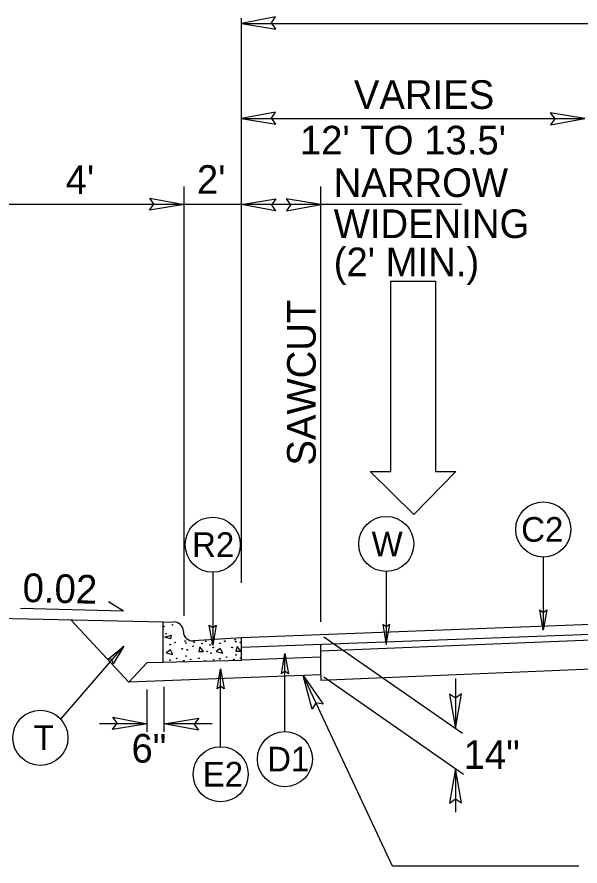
# Model space of a CAD drawing. Extents: x 573748 to 574632, y -54663 to -53209.
# Drawn here: x 574117.58 to 574147.08, y -53400.41 to -53355.94 of the extents above; entities that cross this region are included whole.
import ezdxf

# ---------------------------------------------------------------- set-up
doc = ezdxf.new("R2010")
doc.units = 0
for name, color, linetype in [('Prop Dimension', 7, 'Continuous'), ('Prop Dimension Text', 7, 'Continuous'), ('Prop Lane Arrow CELL', 7, 'Continuous'), ('Prop Terminator CELL', 7, 'Continuous'), ('Typical Arrow Superelevation CELL', 7, 'Continuous'), ('Typical Curb CELL', 7, 'Continuous'), ('Typical ID Circle CELL', 7, 'Continuous'), ('Typical Pavement Slope CELL', 7, 'Continuous'), ('Typical Terminator CELL', 7, 'Continuous'), ('Typical Text ID Circle CELL', 7, 'Continuous')]:
    doc.layers.add(name, color=color, linetype=linetype)

msp = doc.modelspace()

# ---------------------------------------------------------------- linework, layer by layer
at = {"layer": 'Prop Dimension'}
for p, q in [((574129.334, -53385.568), (574129.334, -53356.007)), ((574129.334, -53356.275), (574174.334, -53356.275)), ((574129.334, -53361.256), (574147.334, -53361.256)), ((574126.334, -53387.309), (574126.334, -53364.825)), ((574133.497, -53387.622), (574133.497, -53364.825)), ((574126.334, -53365.76), (574115.581, -53365.76)), ((574140.869, -53365.76), (574126.334, -53365.76)), ((574133.497, -53389.142), (574174.334, -53387.48)), ((574133.65, -53388.4), (574140.917, -53393.451)), ((574133.497, -53390.664), (574174.334, -53389.002)), ((574133.497, -53390.399), (574133.497, -53390.664)), ((574133.647, -53390.503), (574140.973, -53395.595)), ((574125.289, -53393.374), (574125.289, -53391.023)), ((574140.555, -53390.592), (574140.555, -53393.199)), ((574124.399, -53393.374), (574124.399, -53391.17)), ((574124.399, -53392.952), (574121.894, -53392.952)), ((574127.8, -53392.952), (574125.289, -53392.952)), ((574140.555, -53395.304), (574140.555, -53397.581))]:
    msp.add_line(p, q, dxfattribs=at)
msp.add_lwpolyline([(574147.019, -53400.406), (574137.257, -53400.406), (574132.566, -53390.434)], dxfattribs=at)
at = {"layer": 'Prop Lane Arrow CELL'}
for p, q in [((574137.158, -53379.752), (574137.158, -53369.777)), ((574137.158, -53369.777), (574139.509, -53369.777)), ((574139.509, -53369.777), (574139.509, -53379.752)), ((574138.369, -53381.997), (574136.089, -53379.752)), ((574136.089, -53379.752), (574137.158, -53379.752)), ((574140.578, -53379.752), (574138.369, -53381.997)), ((574139.509, -53379.752), (574140.578, -53379.752))]:
    msp.add_line(p, q, dxfattribs=at)
at = {"layer": 'Prop Terminator CELL'}
for points in [[(574131.13, -53355.941), (574129.334, -53356.275), (574131.148, -53356.571), (574130.914, -53356.254)], [(574131.13, -53360.923), (574129.334, -53361.256), (574131.148, -53361.553), (574130.914, -53361.236)], [(574145.537, -53361.589), (574147.334, -53361.256), (574145.519, -53360.959), (574145.753, -53361.277)], [(574124.537, -53365.427), (574126.334, -53365.76), (574124.519, -53366.057), (574124.753, -53365.74)], [(574131.13, -53366.093), (574129.334, -53365.76), (574131.148, -53365.463), (574130.914, -53365.78)], [(574131.701, -53366.093), (574133.497, -53365.76), (574131.682, -53365.463), (574131.917, -53365.78)], [(574133.052, -53392.195), (574132.566, -53390.434), (574133.626, -53391.936), (574133.239, -53391.864)], [(574140.245, -53391.398), (574140.555, -53393.199), (574140.875, -53391.388), (574140.555, -53391.618)], [(574122.602, -53392.619), (574124.399, -53392.952), (574122.584, -53393.249), (574122.818, -53392.932)], [(574127.085, -53393.285), (574125.289, -53392.952), (574127.104, -53392.655), (574126.869, -53392.972)], [(574140.865, -53397.105), (574140.555, -53395.304), (574140.235, -53397.115), (574140.555, -53396.884)]]:
    msp.add_lwpolyline(points, close=True, dxfattribs=at)
at = {"layer": 'Typical Arrow Superelevation CELL'}
for q in [(574122.37, -53386.577), (574117.757, -53386.913)]:
    msp.add_line((574123.15, -53387.055), q, dxfattribs=at)
at = {"layer": 'Typical Curb CELL'}
for p, q in [((574125.235, -53387.633), (574125.78, -53387.619)), ((574125.235, -53389.729), (574125.235, -53387.633)), ((574125.332, -53388.423), (574125.652, -53388.321)), ((574125.652, -53388.321), (574125.622, -53388.512)), ((574126.296, -53388.13), (574126.295, -53388.108)), ((574125.622, -53388.512), (574125.332, -53388.423)), ((574129.334, -53388.449), (574126.832, -53388.618)), ((574129.334, -53389.623), (574129.334, -53388.449)), ((574125.613, -53389.084), (574125.401, -53389.247)), ((574125.401, -53389.247), (574125.75, -53389.321)), ((574125.75, -53389.321), (574125.613, -53389.084)), ((574127.164, -53388.926), (574127.098, -53389.166)), ((574127.098, -53389.166), (574127.349, -53389.173)), ((574127.349, -53389.173), (574127.164, -53388.926)), ((574128.23, -53389.017), (574128.018, -53389.179)), ((574128.018, -53389.179), (574128.367, -53389.253)), ((574128.367, -53389.253), (574128.23, -53389.017)), ((574129.113, -53388.911), (574129.048, -53389.151)), ((574129.048, -53389.151), (574129.301, -53389.158)), ((574129.301, -53389.158), (574129.113, -53388.911)), ((574125.235, -53389.729), (574129.334, -53389.623)), ((574124.397, -53389.751), (574125.235, -53389.729))]:
    msp.add_line(p, q, dxfattribs=at)
for centre in [(574125.269, -53387.863), (574125.721, -53387.779), (574125.386, -53388.243), (574125.605, -53388.81), (574125.853, -53388.697), (574126.39, -53388.624), (574126.428, -53388.728), (574126.858, -53388.684), (574127.267, -53388.755), (574127.467, -53388.637), (574127.7, -53388.827), (574127.815, -53388.753), (574128.222, -53388.742), (574128.47, -53388.63), (574129.007, -53388.556), (574129.046, -53388.661), (574129.284, -53388.692), (574126.233, -53389.033), (574126.497, -53389.086), (574126.804, -53388.898), (574127.541, -53389.167), (574127.745, -53389.257), (574127.856, -53388.955), (574128.85, -53388.965), (574125.59, -53389.624), (574125.946, -53389.531), (574126.321, -53389.653), (574126.434, -53389.411), (574126.678, -53389.584), (574127.107, -53389.525), (574127.446, -53389.66), (574127.885, -53389.601), (574128.207, -53389.556), (574128.564, -53389.463), (574128.938, -53389.585), (574129.051, -53389.343), (574129.295, -53389.516)]:
    msp.add_circle(centre, 0.0168, dxfattribs=at)
for centre, start, end in [((574125.793, -53388.121), 1.4804, 91.4804), ((574126.798, -53388.117), 181.4804, 273.8649)]:
    msp.add_arc(centre, 0.502, start, end, dxfattribs=at)
at = {"layer": 'Typical ID Circle CELL'}
for p, q in [((574145.155, -53384.223), (574145.155, -53388.05)), ((574127.832, -53385.02), (574127.832, -53388.846)), ((574136.926, -53384.984), (574136.926, -53388.81)), ((574119.868, -53392.719), (574123.174, -53388.897)), ((574131.614, -53393.366), (574131.614, -53389.282)), ((574128.249, -53394.158), (574128.249, -53390.074))]:
    msp.add_line(p, q, dxfattribs=at)
for centre in [(574145.155, -53382.781), (574127.833, -53383.577), (574136.926, -53383.541), (574118.802, -53393.69), (574131.614, -53394.809), (574128.249, -53395.6)]:
    msp.add_circle(centre, 1.443, dxfattribs=at)
at = {"layer": 'Typical Pavement Slope CELL'}
for p, q in [((574125.235, -53387.633), (574115.581, -53387.42)), ((574166.834, -53387.046), (574129.334, -53388.449)), ((574174.334, -53387.28), (574129.347, -53388.963)), ((574123.443, -53390.775), (574120.416, -53387.527)), ((574133.497, -53390.399), (574133.497, -53388.808)), ((574133.497, -53389.468), (574129.364, -53389.623)), ((574123.443, -53390.775), (574124.397, -53389.751)), ((574133.497, -53390.399), (574123.443, -53390.775))]:
    msp.add_line(p, q, dxfattribs=at)
at = {"layer": 'Typical Terminator CELL'}
for points in [[(574145.337, -53386.995), (574145.155, -53388.05), (574144.967, -53386.989), (574145.155, -53387.124)], [(574128.014, -53387.792), (574127.832, -53388.846), (574127.645, -53387.786), (574127.832, -53387.921)], [(574136.744, -53387.756), (574136.926, -53388.81), (574137.113, -53387.75), (574136.926, -53387.885)], [(574122.347, -53389.576), (574123.174, -53388.897), (574122.622, -53389.822), (574122.569, -53389.598)], [(574131.433, -53390.337), (574131.614, -53389.282), (574131.802, -53390.343), (574131.614, -53390.208)], [(574128.068, -53391.129), (574128.249, -53390.074), (574128.437, -53391.135), (574128.249, -53391)]]:
    msp.add_lwpolyline(points, close=True, dxfattribs=at)

# ---------------------------------------------------------------- texts
at = {"layer": 'Prop Dimension Text'}
for s, p in [('VARIES', (574135.23, -53360.755)), ("12' TO 13.5'", (574132.399, -53363.142)), ("4'", (574120.127, -53365.211)), ("2'", (574127.004, -53365.203)), ('NARROW', (574134.171, -53365.368)), ('WIDENING', (574134.171, -53367.518)), ("(2' MIN.)", (574134.171, -53369.518)), ('6"', (574123.578, -53394.99)), ('14"', (574140.979, -53395.318))]:
    msp.add_text(s, height=1.5, dxfattribs=at).set_placement(p)
for s, rotation, p in [('SAWCUT', 90, (574133.23, -53379.436)), ('0.02', 358.4883, (574117.857, -53386.573))]:
    msp.add_text(s, height=1.5, rotation=rotation, dxfattribs=at).set_placement(p)
at = {"layer": 'Typical Text ID Circle CELL'}
for s, height, p in [('C2', 1.2912, (574143.997, -53383.424)), ('R2', 1.2912, (574126.754, -53384.22)), ('W', 1.291, (574136.159, -53384.184)), ('T', 1.291, (574118.451, -53394.333)), ('D1', 1.2912, (574130.686, -53395.451)), ('E2', 1.2912, (574127.312, -53396.243))]:
    msp.add_text(s, height=height, dxfattribs=at).set_placement(p)

doc.saveas('drawing.dxf')
